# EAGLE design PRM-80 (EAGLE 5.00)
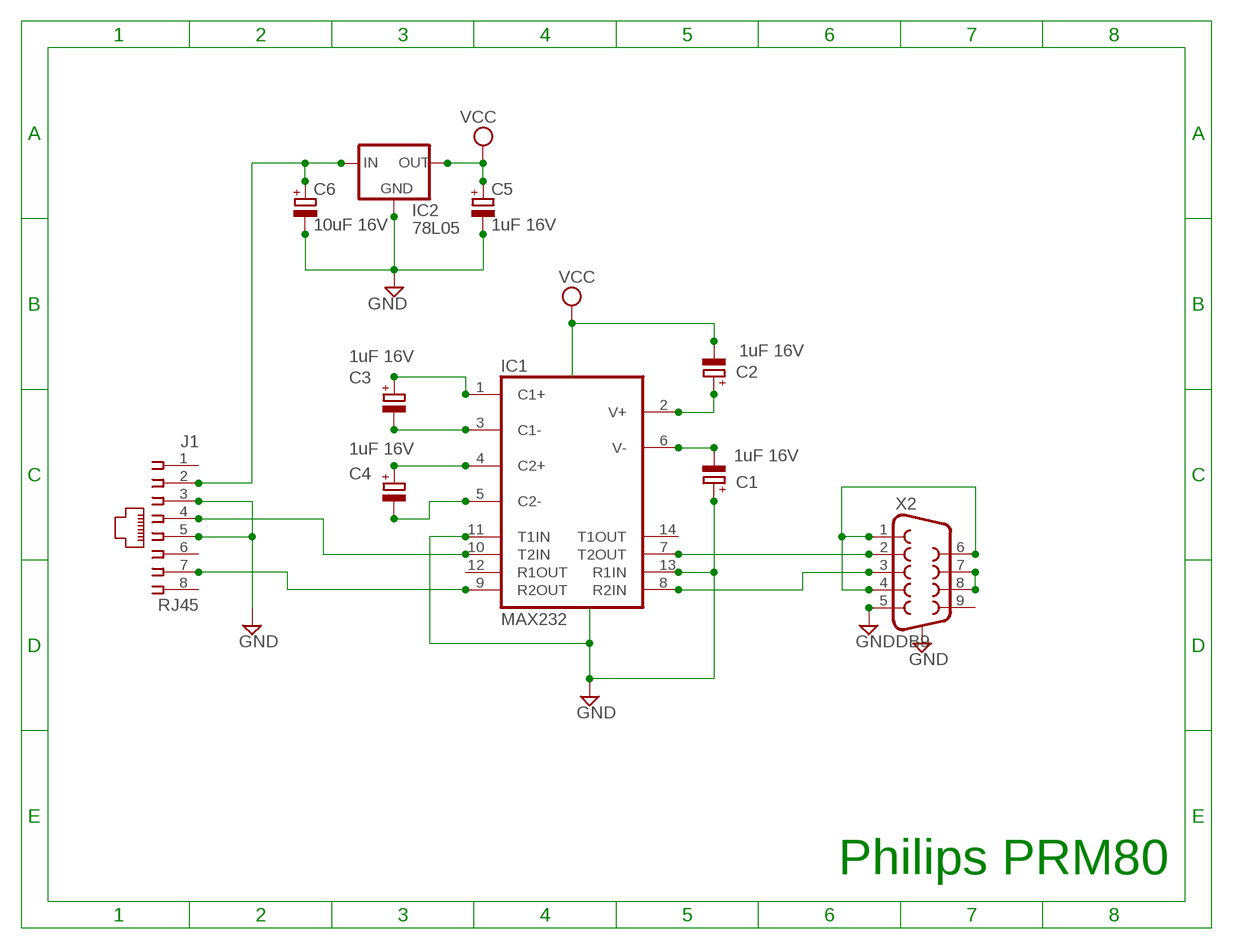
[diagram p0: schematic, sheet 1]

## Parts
C1  1uF 16V  CPOL-EUE2-4  [E2-4]
C2  1uF 16V  CPOL-EUE2-4  [E2-4]
C3  1uF 16V  CPOL-EUE2-4  [E2-4]
C4  1uF 16V  CPOL-EUE2-4  [E2-4]
C5  1uF 16V  CPOL-EUE2-5  [E2-5]
C6  10uF 16V  CPOL-EUE2-5  [E2-5]
IC1  MAX232  [DIL16]
IC2  78L05  78LXX  [78LXX]
J1  RJ45  555164-1  [555164-1]
X2  DB9  F09HP  [F09HP]

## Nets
GND: C1.+ C5.- C6.- IC1.11(T1IN) IC1.13(R1IN) IC2.GND J1.3 J1.5 X2.5
N$1: IC1.9(R2OUT) J1.7
N$2: IC1.7(T2OUT) X2.2
N$3: IC1.8(R2IN) X2.3
N$4: C4.- IC1.5(C2-)
N$5: C3.+ IC1.1(C1+)
N$6: C2.+ IC1.2(V+)
N$7: C3.- IC1.3(C1-)
N$8: C4.+ IC1.4(C2+)
N$9: IC1.10(T2IN) J1.4
N$10: X2.7 X2.8
N$11: C1.- IC1.6(V-)
N$13: C6.+ IC2.IN J1.2
N$14: X2.1 X2.4 X2.6
VCC: C2.- C5.+ IC2.OUT
Unconnected: IC1.12(R1OUT) IC1.14(T1OUT) J1.1 J1.6 J1.8 X2.9

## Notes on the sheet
- Philips PRM80

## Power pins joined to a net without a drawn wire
GND: IC1.15(GND)
VCC: IC1.16(VCC)

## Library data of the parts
C1-C6 = rcl:CPOL-EU: POLARIZED CAPACITOR, European symbol
IC1 = maxim:MAX232: RS232 TRANSEIVER
IC2 = v-reg:78LXX: VOLTAGE REGULATOR
J1 = con-amp:555164-1: AMP connector
X2 = con-subd:F09: SUB-D

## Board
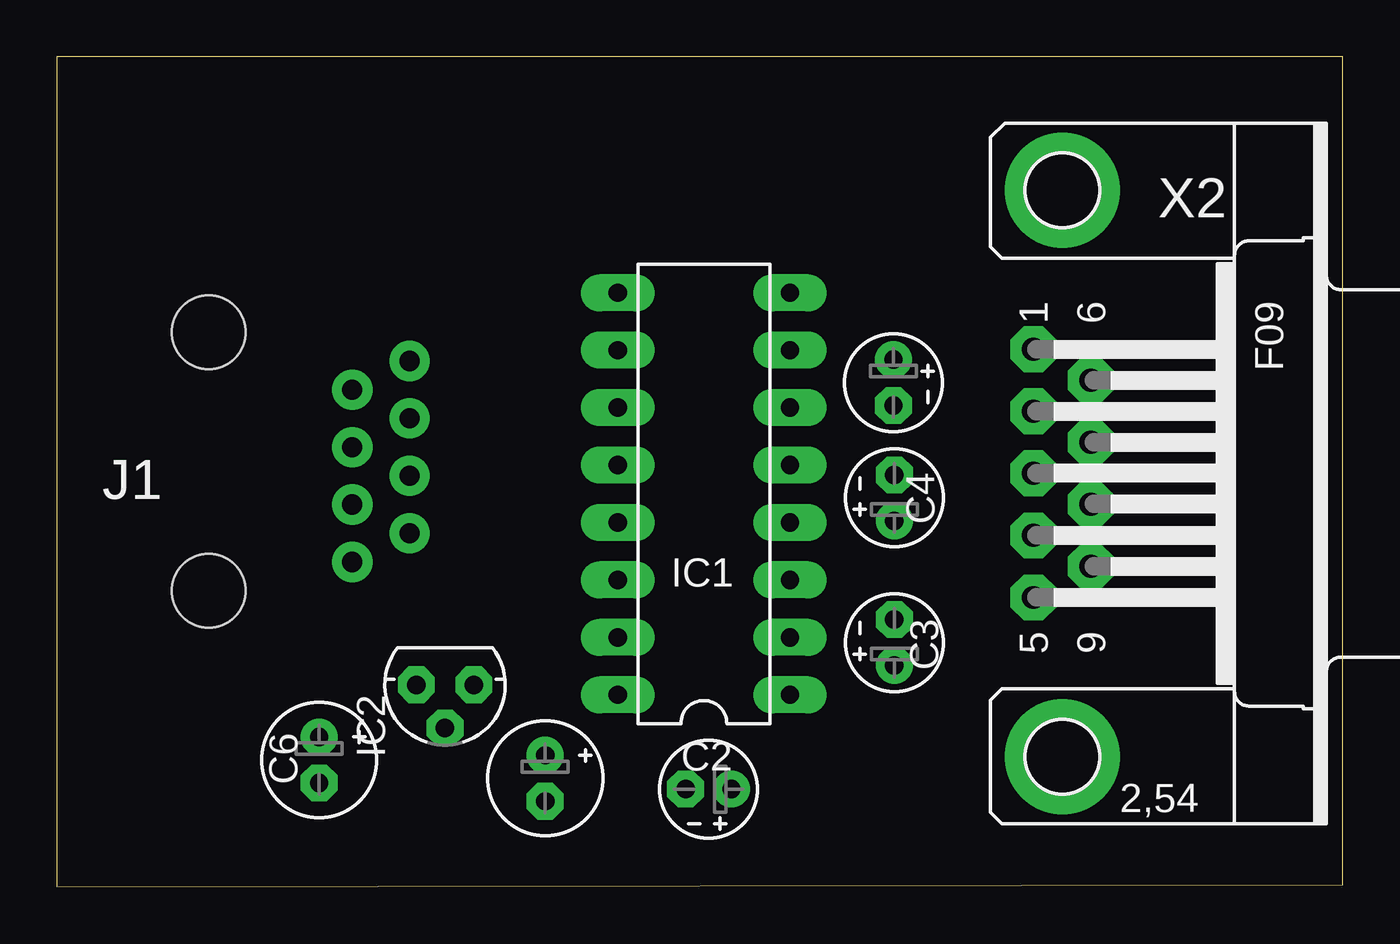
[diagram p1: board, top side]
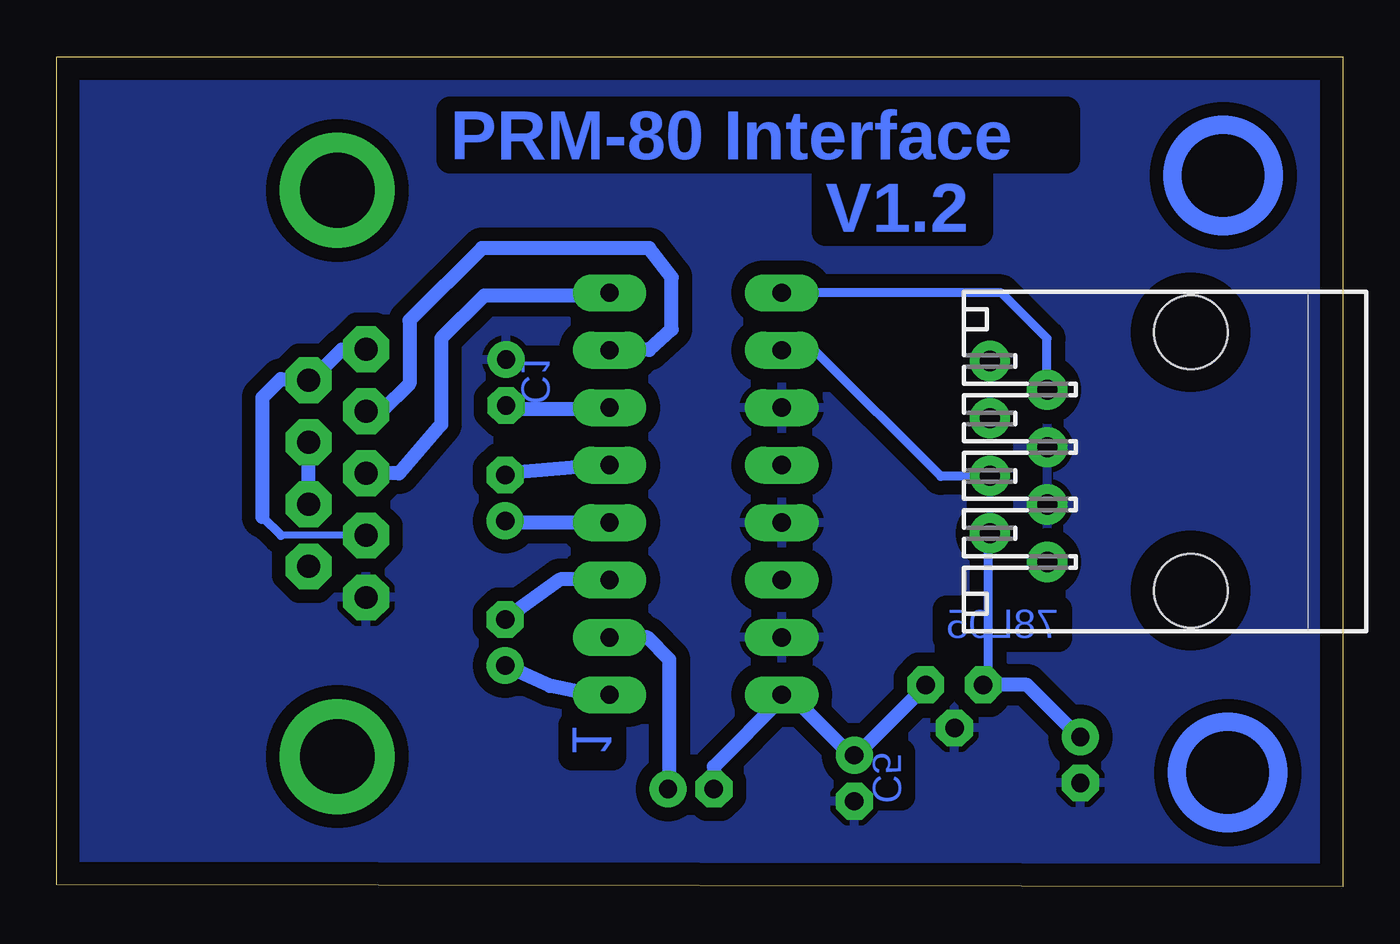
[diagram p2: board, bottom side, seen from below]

Size 56.92 x 36.73 mm. Coordinates in mm from the lower left corner, seen from the top.
Outline: 0,0 56.92,0.1 56.92,36.73 0,36.73 0,0
Copper layers (1*16): Top 0.035mm / dielectric 1.5mm / Bottom 0.035mm
Design rules "default *": minimum track width 10mil, minimum drill 24mil, track to track 8mil, track to pad 8mil, pad to pad 8mil, via to via 8mil, smd to smd 8mil, copper to edge 40mil, drill to drill 8mil, minimum pad ring 10mil, minimum via ring 8mil, stop-mask expansion 4mil, vias tented up to drill 0mil, thermal gap 10mil

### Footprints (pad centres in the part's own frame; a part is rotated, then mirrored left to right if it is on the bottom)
E2-4 = drill 0.813 pad 1.27 round: + -1.016,0 | drill 0.813 pad 1.27 octagon: - 1.016,0
E2-5 = drill 0.813 pad 1.27 round: + -1.016,0 | drill 0.813 pad 1.27 octagon: - 1.016,0
DIL16 = drill 0.813 long: 1 -8.89,-3.81; 2 -6.35,-3.81; 3 -3.81,-3.81; 4 -1.27,-3.81; 5 1.27,-3.81; 6 3.81,-3.81; 7 6.35,-3.81; 8 8.89,-3.81; 9 8.89,3.81; 10 6.35,3.81; 11 3.81,3.81; 12 1.27,3.81; 13 -1.27,3.81; 14 -3.81,3.81; 15 -6.35,3.81; 16 -8.89,3.81
78LXX = drill 0.813 octagon: GND 0,1.905; IN 1.27,0; OUT -1.27,0
555164-1 = drill 0.889 round: 1 -4.445,5.207; 2 -3.175,7.747; 3 -1.905,5.207; 4 -0.635,7.747; 5 0.635,5.207; 6 1.905,7.747; 7 3.175,5.207; 8 4.445,7.747 | hole 3.251: -5.715,-1.143; 5.715,-1.143
F09HP = drill 1.016 octagon: 1 -5.486,-1.27; 2 -2.743,-1.27; 3 0,-1.27; 4 2.743,-1.27; 5 5.486,-1.27; 6 -4.115,1.27; 7 -1.372,1.27; 8 1.372,1.27; 9 4.115,1.27 | drill 3.302 pad 5.08 round: G1 -12.522,0; G2 12.522,0

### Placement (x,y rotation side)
C1  37.03,22.31 270 top
C2  28.85,4.33 180 top
C3  37.07,10.81 90 top
C4  37.07,17.21 90 top
C5  21.62,4.81 270 top
C6  11.62,5.62 270 top
IC1  28.64,17.39 90 top
IC2  17.19,8.94 180 top
J1  7.88,18.82 90 bottom
X2  44.5,18.29 270 top

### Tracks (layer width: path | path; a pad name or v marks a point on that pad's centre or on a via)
GND
  Bottom 0.406: C1.+ 37.3,23.27
  pour Bottom (isolate 0.61): 0.6,36.16 0.4,0.26 56.7,-0.04 56.9,2.06 56.7,4.96 56.4,36.16
N$1
  Bottom 0.406: IC1.9 15.12,26.28 13.1,24.26 13.1,22.16 13.09,22.15 J1.7
N$2
  Bottom 0.406: 32.5,23.76 32.48,23.74 IC1.7
  Bottom 0.61: X2.2 42.53,21.03 41.3,22.26 41.3,25.06 38.1,28.26 30.7,28.26 29.7,26.96 29.7,24.66 30.7,23.76 32.5,23.76
N$3
  Bottom 0.406: 32.5,26.36 32.45,26.31 IC1.8
  Bottom 0.61: X2.3 41.77,18.29 39.9,20.46 39.9,24.26 38,26.16 32.7,26.16 32.5,26.36
N$4
  Bottom 0.406: 37,18.29 C4.-
  Bottom 0.61: 37,18.29 33.62,18.59 IC1.5
N$5
  Bottom 0.254: 37.1,9.8 C3.+
  Bottom 0.61: 37.1,9.8 35.09,8.9 33.32,8.53 IC1.1
N$6
  Bottom 0.406: C2.+
  Bottom 0.61: IC1.2 30.78,11.04 29.8,10.06 29.8,4.66 C2.+
N$7
  Bottom 0.406: 37.1,11.84 C3.-
  Bottom 0.61: 37.1,11.84 34.63,13.61 33.32,13.61 IC1.3
N$8
  Bottom 0.406: 32.49,16.12 33.22,16.05 IC1.4 | 37.1,16.12 C4.+
  Bottom 0.61: 32.49,16.12 37.1,16.12
N$9
  Bottom 0.406: IC1.10 23.38,23.74 17.8,18.16 15.5,18.16 15.53,18.18 J1.4
N$10
  Bottom 0.406: 45.6,16.86 45.66,16.92 45.77,17.03
  Bottom 0.61: X2.8 45.66,16.92 | 45.77,17.03 X2.7
N$11
  Bottom 0.406: 36.83,21.13 37.1,21.2
  Bottom 0.61: 36.83,21.13 32.82,21.13 IC1.6 | 37.1,21.2 C1.-
N$13
  Bottom 0.406: 15.7,15.64 15.7,15.66 | 15.7,15.64 J1.2 | IC2.IN 15.7,8.94 15.7,15.64
  Bottom 0.61: C6.+ 11.68,6.64 13.98,8.94 IC2.IN
N$14
  Bottom 0.305: X2.4 46.99,15.55
  Bottom 0.406: 45.7,22.36 45.74,22.41 X2.6 45.75,22.41 45.7,22.46 | 46.99,15.55 47.8,16.36
  Bottom 0.61: X2.1 44.28,23.78 45.7,22.36 | 47.8,16.36 47.8,21.66 47,22.46 45.7,22.46
VCC
  Bottom 0.61: C2.- 27.83,5.33 24.8,8.36 24.83,8.39 IC1.16 24.44,8.5 21.77,5.83 C5.+ 21.53,5.83 18.42,8.94 | 18.42,8.94 18.3,9.06 | 18.42,8.94 IC2.OUT
(copper drawn outside any net)
  shapes: Bottom circle x2

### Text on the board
Bottom: PRM-80 Interface | V1.2 | 1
